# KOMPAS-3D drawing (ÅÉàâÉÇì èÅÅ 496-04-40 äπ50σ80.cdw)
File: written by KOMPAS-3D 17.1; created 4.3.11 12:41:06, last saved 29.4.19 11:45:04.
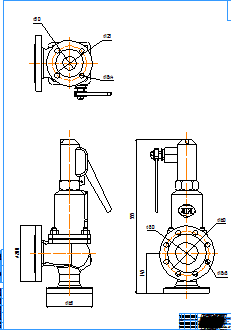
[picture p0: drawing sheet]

Sheet 1: A0, portrait

Title block, sheet 1: name: ПРЕГРАН КПП 496-04-40 Ду50х80; material: Внимание! Данный продукт является объектом авторского права ООО «Торговый Дом АДЛ». / Запрещается изменение, копирование, распространение / (в том числе путем копирования на другие сайты и ресурсы в Интернете) / или любое иное использование информации и объектов без предварительного / согласия правообладателя (ООО «Торговый Дом АДЛ»).; mass: 28,68; sheets: 1; organisation: ООО "Торговый дом АДЛ"; sheet format: A0; stored path: C:\Users\tra\Desktop\2д чертежи\Предохранительные клапаны ПРЕГРАН\ПРЕГРАН 496\ПРЕГРАН КПП 496-04-40\KOMPAS 2D\Прегран Ду 50х80.cdw

Views: Спереди 1, Проекционный вид 2, Проекционный вид 3
Dimensions and other numbers on the sheet: 200; 165; 145; 555; 160; 18; 80; 125; 50; 1:1; 1; 28,68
